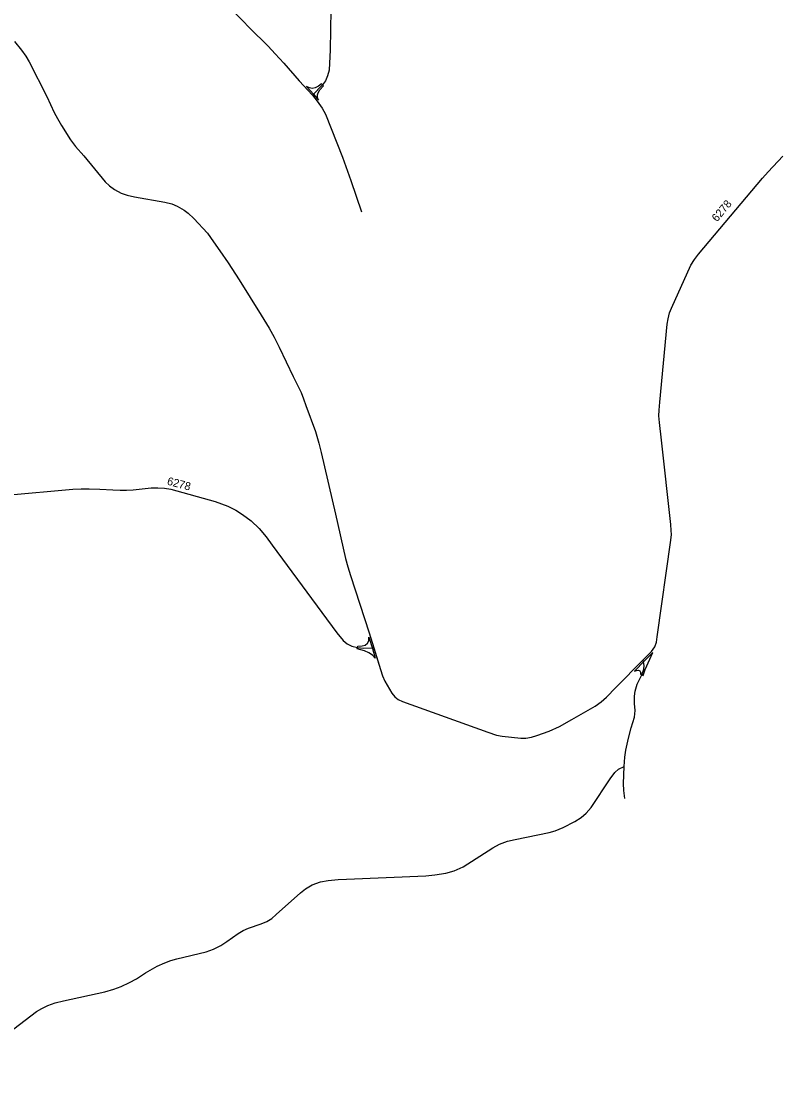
# Model space of a CAD drawing. Extents: x -546703 to -534152, y -1046534 to -1035676.
# Drawn here: x -542791 to -541839, y -1044835 to -1043512 of the extents above; entities that cross this region are included whole.
import ezdxf

# ---------------------------------------------------------------- set-up
doc = ezdxf.new("R2010")
doc.units = 0
doc.layers.add('Vrstva 11', color=7, linetype='Continuous')
doc.layers.add('Vrstva 22', color=7, linetype='Continuous')

msp = doc.modelspace()

# ---------------------------------------------------------------- linework, layer by layer
at = {"layer": 'Vrstva 11'}
for points in [[(-542639, -1043388.9), (-542598.8, -1043429), (-542520, -1043505.1), (-542514.1, -1043511.3), (-542505.2, -1043520.8), (-542481.9, -1043543.7), (-542473, -1043553), (-542462.5, -1043564.8), (-542443, -1043586.9), (-542426.6, -1043604.8), (-542420.5, -1043612.3), (-542414.3, -1043621), (-542410.2, -1043628.7), (-542388.8, -1043682.2), (-542378.4, -1043711.5), (-542365.3, -1043750.4)], [(-542403.6, -1043498.3), (-542404.5, -1043548.2), (-542405.6, -1043573.5), (-542407.6, -1043580.8), (-542410.3, -1043586.9), (-542414, -1043591.8), (-542426.6, -1043604.8)], [(-542798.9, -1043537.6), (-542790, -1043548.6), (-542784.9, -1043556.1), (-542780.4, -1043563.3), (-542758.4, -1043606.6), (-542749.1, -1043626.3), (-542745.1, -1043633.8), (-542740.1, -1043642.6), (-542728.9, -1043660.7), (-542722.6, -1043668.9), (-542712.4, -1043680.6), (-542685.4, -1043712.9), (-542680.2, -1043718.1), (-542673.9, -1043722.5), (-542665.7, -1043727.2), (-542658.1, -1043729.8), (-542649.1, -1043731.6), (-542610.8, -1043738.4), (-542602.3, -1043740.7), (-542595.4, -1043743.6), (-542586.8, -1043748.4), (-542581.7, -1043752.1), (-542574.7, -1043758.7), (-542557.8, -1043777.1), (-542550, -1043787.8), (-542542.1, -1043799.2), (-542531.7, -1043814.2), (-542518, -1043835.3), (-542490.7, -1043879.6), (-542480.8, -1043895.8), (-542474.4, -1043907.2), (-542468.2, -1043919.5), (-542450.6, -1043956.1), (-542440.7, -1043976.4), (-542437.6, -1043984.1), (-542434.7, -1043992.4), (-542422.9, -1044025), (-542418.7, -1044039.7), (-542415.8, -1044051.2), (-542397.8, -1044128.4), (-542385.4, -1044183.8), (-542382.5, -1044194.1), (-542379.1, -1044204.9), (-542355.5, -1044276.6), (-542349.8, -1044295.3), (-542341.6, -1044322.4), (-542339, -1044330.2), (-542335.9, -1044337), (-542327.4, -1044351.7), (-542323.6, -1044356.4), (-542319.5, -1044359.7), (-542314.1, -1044362.4), (-542207.4, -1044400.7), (-542196.6, -1044404.2), (-542189.5, -1044405.5), (-542166.2, -1044408.1), (-542159.7, -1044408), (-542152.7, -1044406.8), (-542146, -1044404.7), (-542130.7, -1044399.2), (-542117.8, -1044393.5), (-542102.4, -1044384.8), (-542073.4, -1044367.9), (-542065.6, -1044362.6), (-542059.1, -1044356.7), (-542047.5, -1044344.9), (-542013.1, -1044310.1), (-542002.7, -1044299.7), (-541998.6, -1044294), (-541996.8, -1044288.2), (-541995.9, -1044281.6), (-541978.5, -1044160.8), (-541977.8, -1044153.8), (-541978.1, -1044148.6), (-541978.9, -1044141), (-541990.3, -1044035.7), (-541993, -1044013.6), (-541993.5, -1044005.4), (-541993.4, -1043998.1), (-541992.3, -1043988.4), (-541983.2, -1043890.8), (-541982.2, -1043884.2), (-541980.3, -1043876.9), (-541977.7, -1043870.7), (-541953.6, -1043817.2), (-541949.3, -1043810.2), (-541944.3, -1043803.5), (-541864.3, -1043708.4), (-541857.2, -1043700.4), (-541838.7, -1043680.9)], [(-542809, -1044104.5), (-542726.1, -1044097), (-542715.7, -1044096.5), (-542705.4, -1044096.4), (-542692.4, -1044096.9), (-542675.9, -1044097.9), (-542666.7, -1044098.4), (-542658.7, -1044098.4), (-542650.5, -1044097.9), (-542627.9, -1044095.4), (-542619.7, -1044095.2), (-542611.3, -1044095.9), (-542603.5, -1044097.2), (-542548, -1044112.6), (-542532.3, -1044118.1), (-542522.1, -1044123.4), (-542513.8, -1044128.7), (-542503.3, -1044136.6), (-542493.3, -1044146.3), (-542484.4, -1044156.4), (-542476.9, -1044166.8), (-542396, -1044276.3), (-542388.3, -1044286), (-542383.3, -1044290.1), (-542377.3, -1044293.1), (-542370.3, -1044294.8), (-542362.7, -1044295.6), (-542349.8, -1044295.3)], [(-542036.3, -1044483.3), (-542037.4, -1044473.3), (-542037.8, -1044464.6), (-542037.2, -1044443.4), (-542036.3, -1044432), (-542035, -1044422.9), (-542031.8, -1044407.9), (-542028.2, -1044395), (-542024.1, -1044381.7), (-542023.4, -1044373.7), (-542023.9, -1044364.6), (-542024.2, -1044355.4), (-542023.4, -1044349.2), (-542020.8, -1044340.5), (-542014.8, -1044329), (-542012.5, -1044322), (-542011.9, -1044317.3), (-542013.1, -1044310.1)], [(-542883.5, -1044834.9), (-542771.4, -1044749.6), (-542764.6, -1044745.6), (-542757.1, -1044742.2), (-542747.9, -1044738.9), (-542737.6, -1044736.1), (-542685.8, -1044724.9), (-542674.8, -1044721.6), (-542665.7, -1044718.2), (-542655.2, -1044713.5), (-542646.4, -1044708.6), (-542635.1, -1044701.3), (-542620.5, -1044693), (-542611, -1044688.7), (-542603.7, -1044686), (-542595.9, -1044683.9), (-542559.2, -1044674.9), (-542550.3, -1044671.5), (-542541.2, -1044667), (-542533.6, -1044662.2), (-542519.5, -1044652), (-542513.2, -1044648.3), (-542506.3, -1044645.5), (-542490.6, -1044640.1), (-542483.5, -1044637.2), (-542477.2, -1044633.3), (-542471.9, -1044628.5), (-542441.6, -1044601.5), (-542435.1, -1044596.2), (-542426.7, -1044591.1), (-542416.6, -1044587.6), (-542406.7, -1044585.9), (-542394.3, -1044584.7), (-542384.1, -1044584.1), (-542284.8, -1044579.9), (-542273.8, -1044578.9), (-542260, -1044576.6), (-542249.4, -1044573.8), (-542238, -1044569), (-542201.2, -1044545), (-542192.8, -1044540.7), (-542182.9, -1044536.9), (-542173.1, -1044534.5), (-542130.6, -1044525.9), (-542123.2, -1044523.9), (-542113.3, -1044519.7), (-542098.5, -1044512.3), (-542090.9, -1044507.3), (-542084.3, -1044501.9), (-542078.4, -1044494.7), (-542054.3, -1044458.9), (-542048.5, -1044451), (-542044, -1044446.8), (-542037.2, -1044443.4)]]:
    msp.add_lwpolyline(points, dxfattribs=at)
for points in [[(-542415.3, -1043590.7), (-542419, -1043593.7), (-542423, -1043595.8), (-542426.9, -1043596.3), (-542430.4, -1043595.8), (-542434.1, -1043594), (-542425.2, -1043603.7), (-542419.1, -1043611.2), (-542420.1, -1043607.7), (-542420.1, -1043604.3), (-542419.3, -1043601.7), (-542417.4, -1043598.2), (-542412.7, -1043592.9)], [(-542370, -1044293.1), (-542364.4, -1044292.8), (-542360.6, -1044291.8), (-542357.7, -1044289.4), (-542355.9, -1044286.3), (-542356, -1044281.9), (-542351.7, -1044295.9), (-542348, -1044308.2), (-542351.5, -1044304.3), (-542355.9, -1044301.3), (-542361.5, -1044298.8), (-542370.6, -1044296.5)], [(-542011.6, -1044311.5), (-542024.3, -1044324.4), (-542021.7, -1044323.4), (-542019.3, -1044323.3), (-542017.4, -1044324.1), (-542016.5, -1044325.5), (-542016.5, -1044328.3), (-542013.2, -1044329.7), (-542010.8, -1044322.4), (-542001.2, -1044301)]]:
    msp.add_lwpolyline(points, close=True, dxfattribs=at)
at = {"layer": 'Vrstva 22'}
for points in [[(-542349.3, -1044296.9), (-542341.6, -1044322.4), (-542339, -1044330.2), (-542335.9, -1044337), (-542327.4, -1044351.7), (-542323.6, -1044356.4), (-542319.5, -1044359.7), (-542314.1, -1044362.4), (-542207.4, -1044400.7), (-542196.6, -1044404.2), (-542189.5, -1044405.5), (-542166.2, -1044408.1), (-542159.7, -1044408), (-542152.7, -1044406.8), (-542146, -1044404.7), (-542130.7, -1044399.2), (-542117.8, -1044393.5), (-542102.4, -1044384.8), (-542073.4, -1044367.9), (-542065.6, -1044362.6), (-542059.1, -1044356.7), (-542047.5, -1044344.9), (-542013.1, -1044310.1), (-542002.7, -1044299.7), (-541998.6, -1044294), (-541996.8, -1044288.2), (-541995.9, -1044281.6), (-541978.5, -1044160.8), (-541977.8, -1044153.8), (-541978.1, -1044148.6), (-541978.9, -1044141), (-541990.3, -1044035.7), (-541993, -1044013.6), (-541993.5, -1044005.4), (-541993.4, -1043998.1), (-541992.3, -1043988.4), (-541983.2, -1043890.8), (-541982.2, -1043884.2), (-541980.3, -1043876.9), (-541977.7, -1043870.7), (-541953.6, -1043817.2), (-541949.3, -1043810.2), (-541944.3, -1043803.5), (-541864.3, -1043708.4), (-541857.2, -1043700.4), (-541838.7, -1043680.9)], [(-542809, -1044104.5), (-542726.1, -1044097), (-542715.7, -1044096.5), (-542705.4, -1044096.4), (-542692.4, -1044096.9), (-542675.9, -1044097.9), (-542666.7, -1044098.4), (-542658.7, -1044098.4), (-542650.5, -1044097.9), (-542627.9, -1044095.4), (-542619.7, -1044095.2), (-542611.3, -1044095.9), (-542603.5, -1044097.2), (-542548, -1044112.6), (-542532.3, -1044118.1), (-542522.1, -1044123.4), (-542513.8, -1044128.7), (-542503.3, -1044136.6), (-542493.3, -1044146.3), (-542484.4, -1044156.4), (-542476.9, -1044166.8), (-542396, -1044276.3), (-542388.3, -1044286), (-542383.3, -1044290.1), (-542377.3, -1044293.1), (-542370.3, -1044294.8), (-542362.7, -1044295.6), (-542349.8, -1044295.3)]]:
    msp.add_lwpolyline(points, dxfattribs=at)

# ---------------------------------------------------------------- texts
for rotation, p in [(49.9234, (-541921, -1043763.7)), (344.9848, (-542608.9, -1044091.2))]:
    msp.add_text('6278', height=10, rotation=rotation, dxfattribs=at).set_placement(p)

doc.saveas('drawing.dxf')
